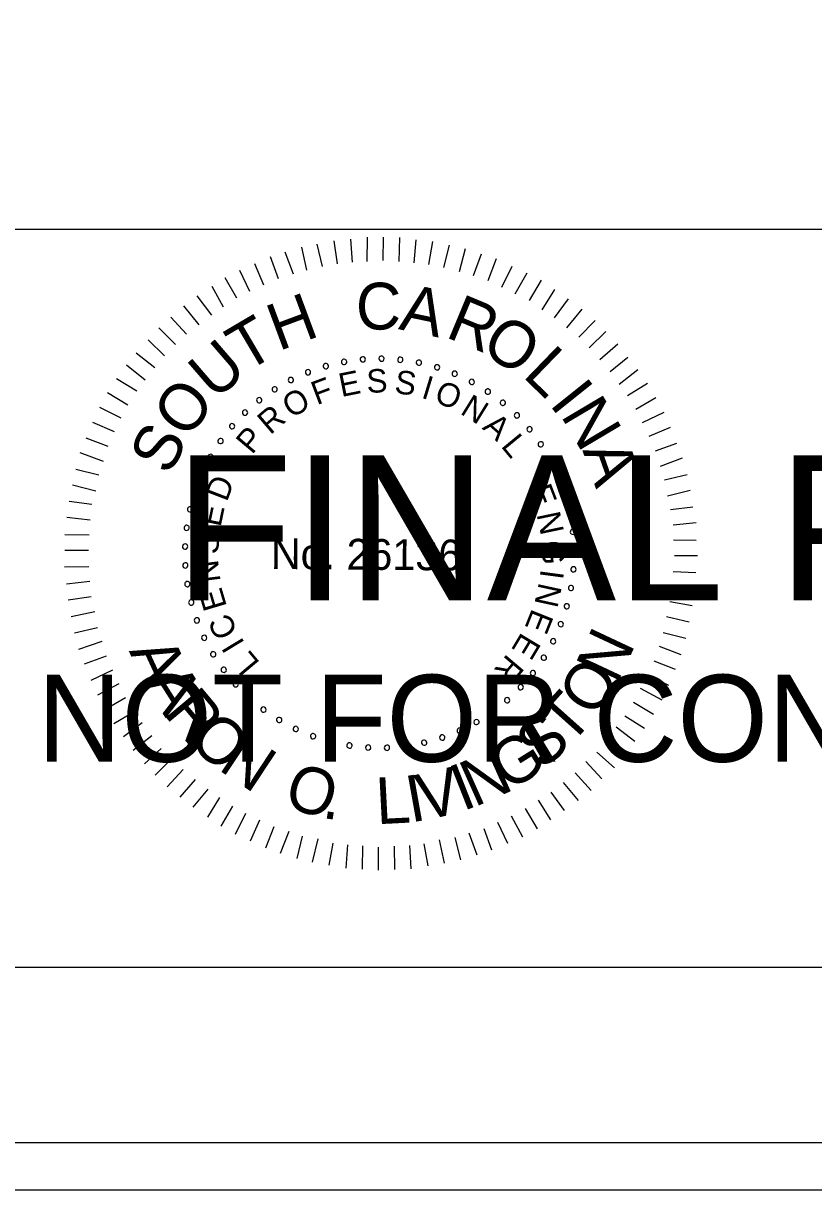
# Model space of a CAD drawing. Extents: x 967 to 1326, y 964 to 2304.
# Drawn here: x 1170.56 to 1189.3, y 963.72 to 991.36 of the extents above; entities that cross this region are included whole.
import ezdxf

# ---------------------------------------------------------------- set-up
doc = ezdxf.new("R2010")
doc.units = 0
for name, color, linetype in [('RD_PD_PaveShd', 7, 'Continuous'), ('RD_XS_Misc_Line', 7, 'Continuous'), ('RD_XS_PaveOvlay', 7, 'Continuous'), ('RD_XS_TX_Elev_EX', 7, 'Continuous'), ('RD_XS_TX_Elev_PR', 7, 'Continuous')]:
    doc.layers.add(name, color=color, linetype=linetype)

msp = doc.modelspace()

# ---------------------------------------------------------------- linework, layer by layer
at = {"layer": 'RD_PD_PaveShd'}
for p, q in [((996.114, 986.486), (1323.886, 986.486)), ((1323.886, 968.983), (996.114, 968.983))]:
    msp.add_line(p, q, dxfattribs=at)
at = {"layer": 'RD_XS_Misc_Line'}
for p, q in [((1178.01, 985.663), (1177.93, 986.209)), ((1178.364, 985.699), (1178.33, 986.244)), ((1178.717, 985.719), (1178.722, 986.295)), ((1179.093, 985.739), (1179.098, 986.292)), ((1179.469, 985.713), (1179.489, 986.288)), ((1179.829, 985.687), (1179.872, 986.231)), ((1180.174, 985.646), (1180.271, 986.19)), ((1176.964, 985.419), (1176.769, 985.935)), ((1177.287, 985.508), (1177.169, 986.054)), ((1177.657, 985.597), (1177.53, 986.128)), ((1180.535, 985.573), (1180.662, 986.102)), ((1180.902, 985.478), (1181.045, 986.022)), ((1176.264, 985.156), (1176.053, 985.657)), ((1176.61, 985.306), (1176.423, 985.83)), ((1181.231, 985.384), (1181.428, 985.896)), ((1181.584, 985.265), (1181.78, 985.786)), ((1175.933, 985.005), (1175.699, 985.506)), ((1181.905, 985.109), (1182.154, 985.606)), ((1182.226, 984.953), (1182.506, 985.45)), ((1175.308, 984.634), (1175.036, 985.12)), ((1175.624, 984.846), (1175.352, 985.332)), ((1182.562, 984.789), (1182.85, 985.27)), ((1175.03, 984.445), (1174.681, 984.9)), ((1182.86, 984.572), (1183.163, 985.053)), ((1183.158, 984.378), (1183.484, 984.828)), ((1174.729, 984.217), (1174.372, 984.665)), ((1183.447, 984.145), (1183.811, 984.587)), ((1174.435, 983.997), (1174.062, 984.399)), ((1183.729, 983.92), (1184.116, 984.316)), ((1174.172, 983.753), (1173.776, 984.148)), ((1183.98, 983.672), (1184.368, 984.061)), ((1173.909, 983.479), (1173.52, 983.858)), ((1184.232, 983.394), (1184.657, 983.767)), ((1173.684, 983.197), (1173.242, 983.546)), ((1184.475, 983.108), (1184.892, 983.45)), ((1173.451, 982.9), (1173.009, 983.256)), ((1184.687, 982.807), (1185.128, 983.156)), ((1173.257, 982.64), (1172.776, 982.936)), ((1173.039, 982.312), (1172.559, 982.6)), ((1184.885, 982.544), (1185.355, 982.832)), ((1185.081, 982.213), (1185.56, 982.493)), ((1172.883, 982.006), (1172.379, 982.256)), ((1185.24, 981.904), (1185.756, 982.145)), ((1172.727, 981.677), (1172.215, 981.904)), ((1185.399, 981.573), (1185.907, 981.791)), ((1172.571, 981.333), (1172.051, 981.53)), ((1185.549, 981.226), (1186.057, 981.414)), ((1172.461, 980.974), (1171.91, 981.178)), ((1185.669, 980.865), (1186.185, 981.06)), ((1172.351, 980.652), (1171.807, 980.787)), ((1185.759, 980.541), (1186.297, 980.667)), ((1172.286, 980.276), (1171.727, 980.419)), ((1185.832, 980.165), (1186.371, 980.298)), ((1172.191, 979.955), (1171.647, 980.029)), ((1185.906, 979.842), (1186.436, 979.906)), ((1172.15, 979.587), (1171.598, 979.653)), ((1185.964, 979.473), (1186.51, 979.53)), ((1172.124, 979.234), (1171.548, 979.239)), ((1185.977, 979.12), (1186.514, 979.115)), ((1172.105, 978.866), (1171.545, 978.871)), ((1185.997, 978.751), (1186.542, 978.747)), ((1172.118, 978.482), (1171.542, 978.471)), ((1185.971, 978.368), (1186.508, 978.348)), ((1172.138, 978.136), (1171.585, 978.072)), ((1185.952, 978.022), (1186.497, 977.949)), ((1172.173, 977.768), (1171.627, 977.688)), ((1185.888, 977.655), (1186.417, 977.566)), ((1172.262, 977.414), (1171.701, 977.296)), ((1185.808, 977.302), (1186.345, 977.175)), ((1172.321, 977.037), (1171.774, 976.911)), ((1185.729, 976.926), (1186.265, 976.792)), ((1172.425, 976.707), (1171.871, 976.519)), ((1185.634, 976.597), (1186.146, 976.401)), ((1172.53, 976.36), (1172.007, 976.173)), ((1185.508, 976.253), (1186.013, 976.057)), ((1172.681, 976.029), (1172.165, 975.788)), ((1172.831, 975.705), (1172.323, 975.441)), ((1185.352, 975.924), (1185.857, 975.675)), ((1185.188, 975.603), (1185.7, 975.33)), ((1172.982, 975.374), (1172.497, 975.094)), ((1185.024, 975.274), (1185.498, 974.987)), ((1173.194, 975.042), (1172.709, 974.762)), ((1184.822, 974.946), (1185.288, 974.658)), ((1173.384, 974.78), (1172.936, 974.453)), ((1184.62, 974.687), (1185.055, 974.353)), ((1173.612, 974.478), (1173.164, 974.129)), ((1184.403, 974.389), (1184.814, 974.033)), ((1173.832, 974.177), (1173.437, 973.812)), ((1184.155, 974.092), (1184.574, 973.72)), ((1174.091, 973.945), (1173.689, 973.541)), ((1183.899, 973.864), (1184.28, 973.454)), ((1174.35, 973.674), (1173.97, 973.263)), ((1183.644, 973.597), (1184.024, 973.18)), ((1174.64, 973.442), (1174.275, 973.022)), ((1174.937, 973.209), (1174.58, 972.782)), ((1183.358, 973.37), (1183.715, 972.944)), ((1175.212, 973.014), (1174.932, 972.549)), ((1182.764, 972.952), (1183.059, 972.482)), ((1183.065, 973.141), (1183.384, 972.709)), ((1175.525, 972.812), (1175.245, 972.331)), ((1182.463, 972.755), (1182.743, 972.269)), ((1175.83, 972.633), (1175.588, 972.136)), ((1176.159, 972.477), (1175.94, 971.98)), ((1181.8, 972.431), (1182.041, 971.93)), ((1182.124, 972.581), (1182.396, 972.08)), ((1176.503, 972.321), (1176.307, 971.816)), ((1176.855, 972.211), (1176.651, 971.69)), ((1177.177, 972.1), (1177.05, 971.572)), ((1181.122, 972.175), (1181.31, 971.652)), ((1181.476, 972.28), (1181.664, 971.771)), ((1177.545, 972.036), (1177.409, 971.484)), ((1177.897, 971.933), (1177.808, 971.412)), ((1178.25, 971.892), (1178.207, 971.34)), ((1178.603, 971.866), (1178.598, 971.313)), ((1178.978, 971.84), (1178.974, 971.295)), ((1179.355, 971.86), (1179.365, 971.307)), ((1179.715, 971.88), (1179.749, 971.327)), ((1180.061, 971.915), (1180.149, 971.393)), ((1180.423, 972.012), (1180.541, 971.458)), ((1180.791, 972.07), (1180.926, 971.54))]:
    msp.add_line(p, q, dxfattribs=at)
for centre, start, end in [((1178.609, 983.397), 5.0653, 185.0653), ((1179.055, 983.414), 359.5268, 179.5268), ((1179.5, 983.388), 353.9884, 173.9884), ((1177.312, 983.091), 21.6807, 201.6807), ((1177.734, 983.235), 16.1422, 196.1422), ((1177.734, 983.235), 196.1422, 16.1422), ((1178.168, 983.337), 10.6038, 190.6038), ((1178.168, 983.337), 190.6038, 10.6038), ((1178.609, 983.397), 185.0653, 5.0653), ((1179.055, 983.414), 179.5268, 359.5268), ((1179.5, 983.388), 173.9884, 353.9884), ((1179.94, 983.319), 168.4499, 348.4499), ((1179.94, 983.319), 348.4499, 168.4499), ((1180.372, 983.208), 162.9114, 342.9114), ((1180.372, 983.208), 342.9114, 162.9114), ((1176.906, 982.908), 27.2191, 207.2191), ((1176.906, 982.908), 207.2191, 27.2191), ((1177.312, 983.091), 201.6807, 21.6807), ((1180.79, 983.056), 157.373, 337.373), ((1180.79, 983.056), 337.373, 157.373), ((1181.193, 982.864), 151.8345, 331.8345), ((1181.193, 982.864), 331.8345, 151.8345), ((1176.52, 982.686), 32.7576, 212.7576), ((1176.52, 982.686), 212.7576, 32.7576), ((1181.574, 982.634), 146.2961, 326.2961), ((1181.574, 982.634), 326.2961, 146.2961), ((1176.156, 982.428), 38.2961, 218.2961), ((1176.156, 982.428), 218.2961, 38.2961), ((1181.932, 982.368), 140.7576, 320.7576), ((1181.932, 982.368), 320.7576, 140.7576), ((1175.82, 982.135), 43.8345, 223.8345), ((1175.82, 982.135), 223.8345, 43.8345), ((1182.263, 982.069), 135.2191, 315.2191), ((1182.263, 982.069), 315.2191, 135.2191), ((1175.513, 981.812), 49.373, 229.373), ((1175.513, 981.812), 229.373, 49.373), ((1182.563, 981.74), 129.6807, 309.6807), ((1182.563, 981.74), 309.6807, 129.6807), ((1175.239, 981.461), 54.9114, 234.9114), ((1175.239, 981.461), 234.9114, 54.9114), ((1182.83, 981.383), 124.1422, 304.1422), ((1182.83, 981.383), 304.1422, 124.1422), ((1175, 981.085), 60.4499, 240.4499), ((1175, 981.085), 240.4499, 60.4499), ((1183.061, 981.002), 118.6038, 298.6038), ((1183.061, 981.002), 298.6038, 118.6038), ((1174.798, 980.687), 65.9884, 245.9884), ((1174.798, 980.687), 245.9884, 65.9884), ((1183.255, 980.601), 293.0653, 113.0653), ((1183.255, 980.601), 113.0653, 293.0653), ((1174.636, 980.272), 71.5268, 251.5268), ((1174.636, 980.272), 251.5268, 71.5268), ((1183.408, 980.182), 107.5268, 287.5268), ((1183.408, 980.182), 287.5268, 107.5268), ((1174.514, 979.843), 77.0653, 257.0653), ((1174.514, 979.843), 257.0653, 77.0653), ((1183.521, 979.751), 101.9884, 281.9884), ((1183.521, 979.751), 281.9884, 101.9884), ((1174.435, 979.405), 82.6038, 262.6038), ((1174.435, 979.405), 262.6038, 82.6038), ((1183.592, 979.311), 96.4499, 276.4499), ((1183.592, 979.311), 276.4499, 96.4499), ((1174.398, 978.961), 88.1422, 268.1422), ((1174.398, 978.961), 268.1422, 88.1422), ((1183.619, 978.866), 90.9114, 270.9114), ((1183.619, 978.866), 270.9114, 90.9114), ((1174.404, 978.515), 93.6807, 273.6807), ((1174.404, 978.515), 273.6807, 93.6807), ((1183.604, 978.421), 85.373, 265.373), ((1183.604, 978.421), 265.373, 85.373), ((1174.453, 978.072), 99.2191, 279.2191), ((1174.453, 978.072), 279.2191, 99.2191), ((1183.546, 977.979), 79.8345, 259.8345), ((1183.546, 977.979), 259.8345, 79.8345), ((1174.545, 977.636), 104.7576, 284.7576), ((1174.545, 977.636), 284.7576, 104.7576), ((1183.445, 977.545), 74.2961, 254.2961), ((1183.445, 977.545), 254.2961, 74.2961), ((1174.678, 977.211), 110.2961, 290.2961), ((1174.678, 977.211), 290.2961, 110.2961), ((1183.303, 977.122), 68.7576, 248.7576), ((1183.303, 977.122), 248.7576, 68.7576), ((1174.852, 976.8), 115.8345, 295.8345), ((1174.852, 976.8), 295.8345, 115.8345), ((1183.121, 976.716), 63.2191, 243.2191), ((1183.121, 976.716), 243.2191, 63.2191), ((1175.065, 976.409), 121.373, 301.373), ((1175.065, 976.409), 301.373, 121.373), ((1182.9, 976.328), 57.6807, 237.6807), ((1182.9, 976.328), 237.6807, 57.6807), ((1175.314, 976.039), 126.9114, 306.9114), ((1175.314, 976.039), 306.9114, 126.9114), ((1182.643, 975.964), 52.1422, 232.1422), ((1182.643, 975.964), 232.1422, 52.1422), ((1175.598, 975.696), 132.4499, 312.4499), ((1175.598, 975.696), 312.4499, 132.4499), ((1182.353, 975.627), 46.6038, 226.6038), ((1175.914, 975.381), 137.9884, 317.9884), ((1175.914, 975.381), 317.9884, 137.9884), ((1182.353, 975.627), 226.6038, 46.6038), ((1176.258, 975.099), 143.5268, 323.5268), ((1176.258, 975.099), 323.5268, 143.5268), ((1182.03, 975.319), 41.0653, 221.0653), ((1182.03, 975.319), 221.0653, 41.0653), ((1176.629, 974.851), 149.0653, 329.0653), ((1176.629, 974.851), 329.0653, 149.0653), ((1181.305, 974.803), 29.9884, 209.9884), ((1181.68, 975.043), 35.5268, 215.5268), ((1181.68, 975.043), 215.5268, 35.5268), ((1177.021, 974.639), 154.6038, 334.6038), ((1177.021, 974.639), 334.6038, 154.6038), ((1180.908, 974.6), 24.4499, 204.4499), ((1180.908, 974.6), 204.4499, 24.4499), ((1181.305, 974.803), 209.9884, 29.9884), ((1177.432, 974.467), 160.1422, 340.1422), ((1177.432, 974.467), 340.1422, 160.1422), ((1177.858, 974.335), 165.6807, 345.6807), ((1177.858, 974.335), 345.6807, 165.6807), ((1178.294, 974.245), 351.2191, 171.2191), ((1180.065, 974.313), 13.373, 193.373), ((1180.065, 974.313), 193.373, 13.373), ((1180.494, 974.436), 18.9114, 198.9114), ((1180.494, 974.436), 198.9114, 18.9114), ((1178.294, 974.245), 171.2191, 351.2191), ((1178.737, 974.198), 356.7576, 176.7576), ((1178.737, 974.198), 176.7576, 356.7576), ((1179.183, 974.193), 2.2961, 182.2961), ((1179.183, 974.193), 182.2961, 2.2961), ((1179.627, 974.232), 7.8345, 187.8345), ((1179.627, 974.232), 187.8345, 7.8345)]:
    msp.add_arc(centre, 0.0627, start, end, dxfattribs=at)
at = {"layer": 'RD_XS_PaveOvlay'}
msp.add_lwpolyline([(967.409, 963.72), (1326.285, 963.72), (1326.285, 1183.72), (967.409, 1183.72)], close=True, dxfattribs=at)
at = {"layer": 'RD_XS_TX_Elev_EX'}
for points in [[(967.409, 963.72), (1326.285, 963.72), (1326.285, 1183.72), (967.409, 1183.72)], [(988.525, 964.84), (1326.285, 964.84), (1326.285, 1182.6), (988.525, 1182.6)]]:
    msp.add_lwpolyline(points, close=True, dxfattribs=at)

# ---------------------------------------------------------------- texts
at = {"layer": 'RD_XS_Misc_Line'}
for s, height, rotation, p in [('C', 1.11, 359.5482, (1178.442, 984.108)), ('A', 1.11, 348.1981, (1179.439, 984.115)), ('H', 1.11, 20.3637, (1176.614, 983.587)), ('R', 1.11, 337.4344, (1180.541, 983.937)), ('T', 1.11, 30.4992, (1175.828, 983.072)), ('O', 1.108, 326.5869, (1181.366, 983.609)), ('U', 1.11, 40.8022, (1175.102, 982.403)), ('L', 1.11, 315.9488, (1182.373, 983.003)), ('S', 0.557, 2.208, (1178.709, 982.601)), ('F', 0.557, 20.6127, (1177.52, 982.309)), ('E', 0.557, 11.4103, (1178.103, 982.503)), ('S', 0.557, 352.6608, (1179.346, 982.599)), ('I', 0.557, 343.1136, (1179.975, 982.491)), ('I', 1.11, 308.6613, (1183.011, 982.338)), ('O', 1.11, 52.0267, (1174.435, 981.474)), ('O', 0.557, 30.8477, (1176.917, 981.987)), ('O', 0.557, 338.4392, (1180.274, 982.401)), ('N', 0.557, 328.2042, (1180.896, 982.12)), ('N', 1.11, 300.7037, (1183.285, 982.075)), ('R', 0.557, 40.3949, (1176.415, 981.594)), ('A', 0.557, 318.657, (1181.424, 981.762)), ('S', 1.108, 63.2511, (1174.029, 980.619)), ('P', 0.557, 49.9421, (1175.985, 981.124)), ('L', 0.557, 309.4546, (1181.869, 981.339)), ('A', 1.11, 289.4792, (1183.814, 981.243)), ('D', 0.557, 69.0364, (1175.386, 980.003)), ('E', 0.557, 291.049, (1182.53, 980.307)), ('E', 0.557, 78.2388, (1175.238, 979.407)), ('N', 0.557, 281.8466, (1182.728, 979.726)), ('S', 0.557, 87.786, (1175.187, 978.772)), ('No. 26136', 0.7311, 359.5268, (1176.429, 978.43)), ('G', 0.557, 272.2995, (1182.833, 979.097)), ('N', 0.557, 97.3332, (1175.242, 978.137)), ('I', 0.557, 262.4084, (1182.83, 978.437)), ('E', 0.557, 106.5355, (1175.394, 977.541)), ('N', 0.557, 257.7339, (1182.789, 978.127)), ('E', 0.557, 248.1867, (1182.628, 977.511)), ('C', 0.557, 116.4266, (1175.661, 976.938)), ('E', 0.557, 238.9844, (1182.378, 976.949)), ('N', 1.105, 64.8922, (1184.632, 975.684)), ('A', 1.105, 294.7297, (1173.062, 976.486)), ('I', 0.557, 121.1011, (1175.823, 976.67)), ('L', 0.557, 129.9595, (1176.187, 976.204)), ('R', 0.557, 229.782, (1182.041, 976.435)), ('O', 1.105, 56.2059, (1184.102, 974.874)), ('A', 1.105, 302.2892, (1173.414, 975.72)), ('R', 1.105, 309.8487, (1173.865, 975.007)), ('T', 1.105, 48.2685, (1183.515, 974.211)), ('O', 1.105, 317.7861, (1174.434, 974.33)), ('S', 1.105, 40.3311, (1182.842, 973.636)), ('N', 1.105, 326.4725, (1175.158, 973.686)), ('G', 1.105, 32.0198, (1182.059, 973.14)), ('N', 1.105, 24.0824, (1181.252, 972.776)), ('O', 1.105, 342.3472, (1176.697, 972.82)), ('V', 1.105, 12.7741, (1180.033, 972.457)), ('I', 1.105, 21.4605, (1180.976, 972.681)), ('L', 1.105, 2.9677, (1178.943, 972.379)), ('I', 1.105, 10.1523, (1179.743, 972.418)), ('.', 1.105, 351.0336, (1177.623, 972.536))]:
    msp.add_text(s, height=height, rotation=rotation, dxfattribs=at).set_placement(p)
at = {"layer": 'RD_XS_TX_Elev_PR'}
for s, height, p in [('FINAL PLANS', 3.4375, (1174.145, 977.685)), ('NOT FOR CONSTRUCTION', 2.0625, (1170.901, 973.86))]:
    msp.add_text(s, height=height, dxfattribs=at).set_placement(p)

doc.saveas('drawing.dxf')
